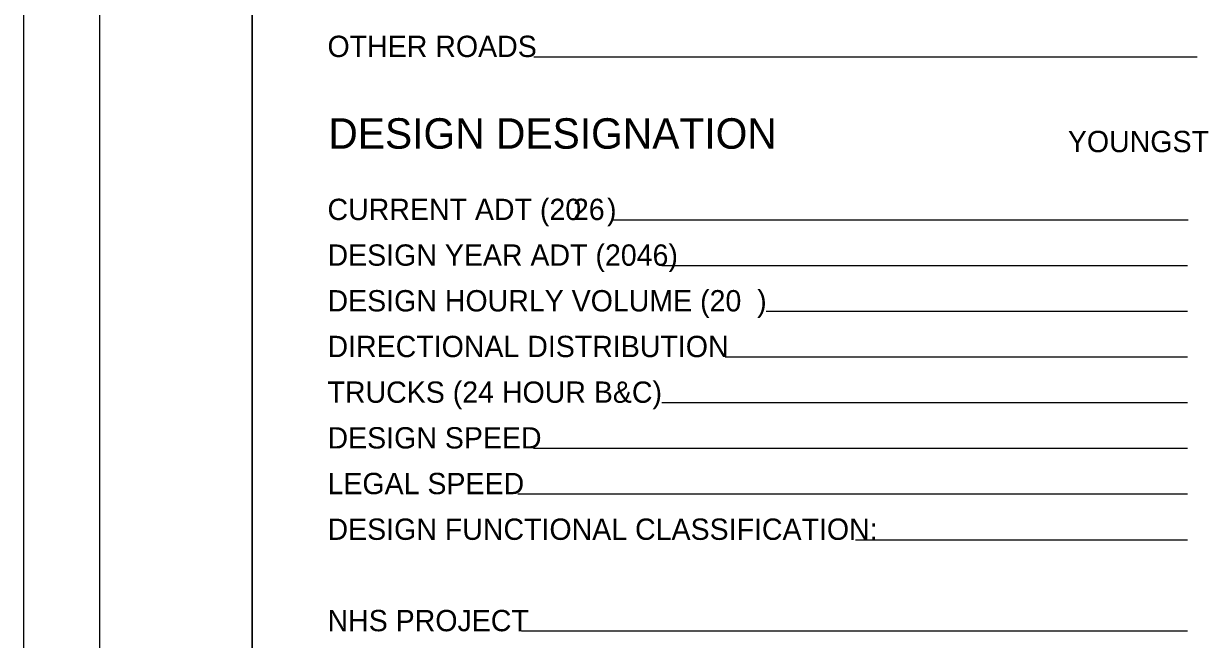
# Model space of a CAD drawing. Extents: x 0 to 34, y 0 to 22.
# Drawn here: x 0 to 7.72, y 7.05 to 11.1 of the extents above; entities that cross this region are included whole.
import ezdxf

# ---------------------------------------------------------------- set-up
doc = ezdxf.new("R2010")
doc.units = 0
for name, color, linetype in [('Default', 7, 'Continuous'), ('SH_Border', 7, 'Continuous'), ('SH_Cut_Line', 7, 'Continuous'), ('SH_Data', 7, 'Continuous'), ('SH_Text', 7, 'Continuous')]:
    doc.layers.add(name, color=color, linetype=linetype)

msp = doc.modelspace()

# ---------------------------------------------------------------- linework, layer by layer
at = {"layer": 'SH_Border'}
for points in [[(0.5, 21.5), (1.5, 21.5), (1.5, 0.5), (0.5, 0.5)], [(1.5, 21.5), (33.5, 21.5), (33.5, 0.5), (1.5, 0.5)]]:
    msp.add_lwpolyline(points, close=True, dxfattribs=at)
at = {"layer": 'SH_Cut_Line'}
msp.add_lwpolyline([(0, 0), (34, 0), (34, 22), (0, 22)], close=True, dxfattribs=at)
at = {"layer": 'SH_Data'}
for p, q in [((7.7, 10.8767), (3.3471, 10.8767)), ((7.6424, 9.8062), (3.871, 9.8062)), ((7.6368, 9.5062), (4.1885, 9.5062)), ((7.6368, 9.2062), (4.8723, 9.2062)), ((7.6368, 8.9062), (4.6037, 8.9062)), ((7.6368, 8.6062), (4.1885, 8.6062)), ((7.6368, 8.3062), (3.346, 8.3062)), ((7.6368, 8.0062), (3.2422, 8.0062)), ((5.4588, 7.7062), (7.6368, 7.7062)), ((7.6368, 7.1062), (3.2669, 7.1062))]:
    msp.add_line(p, q, dxfattribs=at)

# ---------------------------------------------------------------- texts
at = {"layer": 'Default'}
msp.add_text('YOUNGSTOWN-SALEM RD', height=0.14, dxfattribs=at).set_placement((6.8521, 10.252))
at = {"layer": 'SH_Data'}
msp.add_text('DESIGN DESIGNATION', height=0.2, dxfattribs=at).set_placement((2, 10.2747))
at = {"layer": 'SH_Text'}
for s, p in [('OTHER ROADS', (1.9944, 10.8767)), ('CURRENT ADT (20', (1.9944, 9.8062)), ('26', (3.6047, 9.8062)), (')', (3.8282, 9.8062)), ('DESIGN YEAR ADT (2046)', (1.9944, 9.5062)), ('DESIGN HOURLY VOLUME (20  )', (1.9944, 9.2062)), ('DIRECTIONAL DISTRIBUTION', (1.9944, 8.9062)), ('TRUCKS (24 HOUR B&C)', (1.9944, 8.6062)), ('DESIGN SPEED', (1.9944, 8.3062)), ('LEGAL SPEED', (1.9944, 8.0062)), ('DESIGN FUNCTIONAL CLASSIFICATION:', (1.9944, 7.7062)), ('NHS PROJECT', (1.9944, 7.1062))]:
    msp.add_text(s, height=0.14, dxfattribs=at).set_placement(p)

doc.saveas('drawing.dxf')
